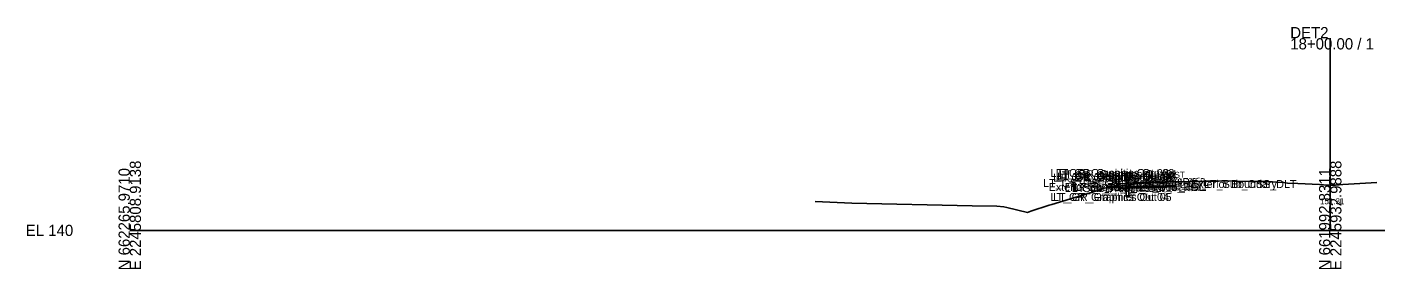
# Model space of a CAD drawing. Extents: x -26 to 603, y -10 to 9526.
# Drawn here: x -25.7 to 311.2, y 990.3 to 1051 of the extents above; entities that cross this region are included whole.
import ezdxf

# ---------------------------------------------------------------- set-up
doc = ezdxf.new("R2010")
doc.units = 0
for name, color, linetype in [('Default', 7, 'Continuous'), ('Exist Cross Section Cell', 7, 'Continuous'), ('Exist XS Center Line Elevation Label', 7, 'Continuous'), ('Exist XS Ground Line', 7, 'Continuous'), ('Prop CMT Guardrail Graphics', 7, 'Continuous'), ('Prop CMT Pvmt Course 1', 7, 'Continuous'), ('Prop CMT Pvmt Course 2', 7, 'Continuous'), ('Prop CMT Pvmt Course 3', 7, 'Continuous'), ('Prop CMT Pvmt Surface', 7, 'Continuous'), ('Prop CMT Pvmt Surface Shoulder', 7, 'Continuous'), ('Prop CMT Shld Paved Course 1', 7, 'Continuous'), ('Prop CMT Shld Paved Course 2', 7, 'Continuous'), ('Prop CMT Shld Paved Course 3', 7, 'Continuous'), ('Prop CMT Slope Grass', 7, 'Continuous'), ('Prop CMT Subgrade Earthwork', 7, 'Continuous'), ('Prop XS SE Text', 7, 'Continuous'), ('Prop XS Side Slope Text', 7, 'Continuous'), ('Scratch_Level_2', 7, 'Continuous')]:
    doc.layers.add(name, color=color, linetype=linetype)

msp = doc.modelspace()

# ---------------------------------------------------------------- linework, layer by layer
at = {"layer": 'Exist Cross Section Cell'}
for p, q in [((300, 1000), (300, 1048.13)), ((0, 1000), (300, 1000)), ((300, 1000), (600, 1000))]:
    msp.add_line(p, q, dxfattribs=at)
at = {"layer": 'Exist XS Ground Line'}
for p, q in [((243.37, 1010.55), (247.67, 1011.19)), ((247.67, 1011.19), (252.64, 1011.86)), ((252.64, 1011.86), (253.12, 1011.86)), ((253.12, 1011.86), (254.21, 1011.88)), ((254.21, 1011.88), (254.57, 1011.89)), ((254.57, 1011.89), (256.44, 1011.96)), ((256.44, 1011.96), (256.84, 1011.98)), ((256.84, 1011.98), (258.58, 1012.03)), ((258.58, 1012.03), (259.05, 1012.15)), ((259.05, 1012.15), (259.78, 1012.16)), ((259.78, 1012.16), (260.92, 1012.17)), ((260.92, 1012.17), (261.33, 1012.16)), ((261.33, 1012.16), (263.16, 1012.19)), ((263.16, 1012.19), (264.67, 1012.23)), ((264.67, 1012.23), (265.89, 1012.26)), ((265.89, 1012.26), (268.59, 1012.3)), ((268.59, 1012.3), (269.67, 1012.32)), ((269.67, 1012.32), (270.16, 1012.33)), ((270.16, 1012.33), (272.11, 1012.37)), ((272.11, 1012.37), (272.92, 1012.4)), ((272.92, 1012.4), (273.63, 1012.45)), ((273.63, 1012.45), (274.26, 1012.38)), ((274.26, 1012.38), (275.65, 1012.34)), ((275.65, 1012.34), (280.68, 1012.25)), ((280.68, 1012.25), (281.14, 1012.24)), ((281.14, 1012.24), (284.16, 1012.23)), ((284.16, 1012.23), (284.53, 1012.23)), ((284.53, 1012.23), (286.63, 1012.08)), ((286.63, 1012.08), (288.37, 1011.96)), ((288.37, 1011.96), (288.94, 1011.89)), ((288.94, 1011.89), (289.33, 1011.84)), ((289.33, 1011.84), (291.88, 1011.73)), ((291.88, 1011.73), (297.28, 1011.5)), ((297.28, 1011.5), (298.3, 1011.43)), ((298.3, 1011.43), (300.21, 1011.3)), ((300.21, 1011.3), (301.29, 1011.37)), ((301.29, 1011.37), (303.16, 1011.48)), ((303.16, 1011.48), (311.64, 1011.98)), ((230.41, 1006.45), (241.65, 1009.95)), ((241.65, 1009.95), (243.37, 1010.55)), ((171.28, 1007.23), (180.44, 1006.86)), ((180.44, 1006.86), (210.52, 1006.16)), ((210.52, 1006.16), (216.65, 1006.03)), ((216.65, 1006.03), (218.41, 1005.93)), ((218.41, 1005.93), (219.19, 1005.74)), ((219.19, 1005.74), (224.34, 1004.48)), ((224.34, 1004.48), (225.19, 1004.79)), ((225.19, 1004.79), (229.76, 1006.34)), ((229.76, 1006.34), (230.41, 1006.45))]:
    msp.add_line(p, q, dxfattribs=at)
at = {"layer": 'Prop CMT Guardrail Graphics'}
for points in [[(248.97, 1008.39), (248.97, 1014.39)], [(248.97, 1014.39), (250.31, 1014.39), (250.58, 1014.1)], [(250.58, 1014.1), (250.31, 1013.81)], [(250.58, 1013.52), (250.31, 1013.22), (249.64, 1013.22)], [(249.64, 1013.22), (249.64, 1008.39)], [(250.31, 1013.81), (250.58, 1013.52)], [(249.64, 1008.39), (248.97, 1008.39)]]:
    msp.add_lwpolyline(points, dxfattribs=at)
at = {"layer": 'Prop CMT Pvmt Course 1'}
for points in [[(261.33, 1012.16), (259.09, 1012.1)], [(259.09, 1012.1), (259.09, 1011.19)], [(259.09, 1011.19), (261.33, 1011.24)], [(261.33, 1011.24), (261.33, 1012.16)]]:
    msp.add_lwpolyline(points, dxfattribs=at)
at = {"layer": 'Prop CMT Pvmt Course 2'}
for points in [[(261.33, 1011.24), (259.09, 1011.19)], [(259.09, 1011.19), (259.09, 1010.85)], [(259.09, 1010.85), (261.33, 1010.91)], [(261.33, 1010.91), (261.33, 1011.24)]]:
    msp.add_lwpolyline(points, dxfattribs=at)
at = {"layer": 'Prop CMT Pvmt Course 3'}
for points in [[(261.33, 1010.91), (259.09, 1010.85)], [(259.09, 1010.85), (261.33, 1010.91)], [(259.09, 1010.85), (259.09, 1010.85)], [(261.33, 1010.91), (261.33, 1010.91)]]:
    msp.add_lwpolyline(points, dxfattribs=at)
at = {"layer": 'Prop CMT Pvmt Surface'}
msp.add_lwpolyline([(261.33, 1012.16), (259.09, 1012.1)], dxfattribs=at)
at = {"layer": 'Prop CMT Pvmt Surface Shoulder'}
msp.add_lwpolyline([(259.09, 1012.1), (250.58, 1011.89)], dxfattribs=at)
at = {"layer": 'Prop CMT Shld Paved Course 1'}
for p, q in [((250.58, 1011.89), (249.64, 1010.95)), ((259.09, 1012.1), (251.22, 1011.91))]:
    msp.add_line(p, q, dxfattribs=at)
for points in [[(250.28, 1010.97), (259.09, 1011.19)], [(259.09, 1011.19), (259.09, 1012.1)]]:
    msp.add_lwpolyline(points, dxfattribs=at)
at = {"layer": 'Prop CMT Shld Paved Course 2'}
for p, q in [((249.64, 1010.95), (249.31, 1010.62)), ((259.09, 1011.19), (249.64, 1010.95))]:
    msp.add_line(p, q, dxfattribs=at)
for points in [[(249.94, 1010.63), (259.09, 1010.85)], [(259.09, 1010.85), (259.09, 1011.19)]]:
    msp.add_lwpolyline(points, dxfattribs=at)
at = {"layer": 'Prop CMT Shld Paved Course 3'}
for points in [[(259.09, 1010.85), (249.94, 1010.63), (249.44, 1010.61)], [(249.44, 1010.61), (259.09, 1010.85)], [(259.09, 1010.85), (259.09, 1010.85)], [(249.44, 1010.61), (249.44, 1010.61)]]:
    msp.add_lwpolyline(points, dxfattribs=at)
at = {"layer": 'Prop CMT Slope Grass'}
for points in [[(247.58, 1011.65), (245.01, 1010.79)], [(250.58, 1011.89), (247.58, 1011.65)]]:
    msp.add_lwpolyline(points, dxfattribs=at)
at = {"layer": 'Prop CMT Subgrade Earthwork'}
for points in [[(249.44, 1010.61), (245.01, 1010.79)], [(259.09, 1010.85), (249.44, 1010.61)], [(261.33, 1010.91), (259.09, 1010.85)]]:
    msp.add_lwpolyline(points, dxfattribs=at)

# ---------------------------------------------------------------- texts
at = {"layer": 'Default'}
msp.add_text('-', height=0.0001, dxfattribs=at).set_placement((0, 1000))
msp.add_text('-', height=0.0001, dxfattribs=at).set_placement((0, 1000))
msp.add_text('-', height=0.0001, dxfattribs=at).set_placement((0, 1000))
msp.add_text('-', height=0.0001, dxfattribs=at).set_placement((0, 1000))
at = {"layer": 'Exist Cross Section Cell'}
for s, p in [('18+00.00 / 1', (290, 1045.33)), ('DET2', (290, 1048.13)), ('EL 140', (-26, 998.6))]:
    msp.add_text(s, height=2.8, dxfattribs=at).set_placement(p)
for s, p in [('N 662265.9710', (0, 990)), ('E 2245808.9138', (2.8, 990)), ('N 661992.8311', (300, 990)), ('E 2245932.9888', (302.8, 990))]:
    msp.add_text(s, height=2.8, rotation=90, dxfattribs=at).set_placement(p)
at = {"layer": 'Exist XS Center Line Elevation Label'}
msp.add_text('151.31', height=1.5, dxfattribs=at).set_placement((297.42, 1006.56))
at = {"layer": 'Prop XS SE Text'}
msp.add_text('EXIST', height=1.5, rotation=1.4321, dxfattribs=at).set_placement((257.87, 1013.07))
at = {"layer": 'Prop XS Side Slope Text'}
msp.add_text('3:1', height=1.5, rotation=18.4332, dxfattribs=at).set_placement((245.68, 1011.68))
at = {"layer": 'Scratch_Level_2'}
for s, p in [('LT_GR_Graphics Out 03', (230.1, 1013.37)), ('LT_GR_Graphics Out 06', (230.72, 1012.21)), ('LT_GR_Graphics Out 02', (231.43, 1013.37)), ('LT_GR_Graphics Out 09', (231.43, 1012.79)), ('LT_GR_Graphics Out 07', (231.43, 1012.21)), ('LT_GR_Graphics Out 08', (231.71, 1012.5)), ('LT_GR_Graphics Out 01', (232.27, 1013.08)), ('LT_GS_OS_GR_Face_Graphics', (228.26, 1010.87)), ('Exterior Boundary', (229.66, 1009.87)), ('LT_Sub_Trench_Out', (233.64, 1009.61)), ('LT_PS3_Shelf_Out', (235.42, 1009.61)), ('LT_Slope_Fill', (236.04, 1009.87)), ('LT_GS_OS_CTL', (237.18, 1010.63)), ('LT_PS3_OEOP', (240.17, 1009.63)), ('LT_PS2_OEOP', (240.51, 1009.97)), ('LT_PS1_OEOP', (242.02, 1010.91)), ('LT_Sub_OEOT', (249.17, 1009.85)), ('LT_PV2_OEOT', (249.26, 1010.19)), ('LT_PV3_OEOT', (249.26, 1009.85)), ('LT_PV1_OEOT', (249.83, 1011.1)), ('LT_Sub_PGL', (252.44, 1009.91)), ('LT_PV2_PGL', (252.54, 1010.24)), ('LT_PV3_PGL', (252.54, 1009.91)), ('LT_PV1_PGL', (253.11, 1011.16)), ('Exterior Boundary', (265.25, 1010.61)), ('LT_Sub_OSS_DLT', (268.51, 1010.61)), ('LT_GR_Graphics Out 04', (230.1, 1007.37)), ('LT_GR_Graphics Out 05', (230.77, 1007.37))]:
    msp.add_text(s, height=2, dxfattribs=at).set_placement(p)

doc.saveas('drawing.dxf')
